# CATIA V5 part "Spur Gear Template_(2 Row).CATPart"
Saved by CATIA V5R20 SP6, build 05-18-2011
Part number: Spur Gear Template_(2 Row)
Bounding box of the stored display mesh (mm): x 0 to 42, y -40.991 to 40.991, z -40.924 to 40.992
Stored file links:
  E:\#01 CATIA Lecture Materials\#06 DMU\#10 Kinematics Joints\#002 Gear Joint(Spur Gear)\Spur Gear Template_(2 Row).CATPart
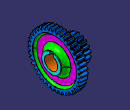
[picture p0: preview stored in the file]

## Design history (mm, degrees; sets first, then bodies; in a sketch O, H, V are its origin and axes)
Set1 "Reference Data"
  Point1 "Center Point": (0, 0, 0)
  Set2 "Datum Plane Body"
    Plane1 "Plane.1(YZ Offset Plane=42mm)": type Offset, RefPlane yz-plane, Offset 42
    Plane2 "Plane.2(Plane1 Offset Plane=-5mm)": type Offset, RefPlane Plane1, Offset -5
    Plane3 "Plane.3(Plane2 Offset Plane=-11mm)": type Offset, RefPlane Plane2, Offset -11
Body1 (main body)
  Body2 "Spur Gear Body(Z=39)"
    Pad1: profile Join2, length 11
    Sketch1 on zx-plane, origin (0, 0, 0), H (-1, 0, 0), V (0, 0, 1)
      axis line L1 (0, 0) -> (6.502, 0)
      line L2 (0, 0) -> (0, 40)
      line L3 (-1, 41) -> (-10, 41)
      line L4 (-11, 40) -> (-11, 0)
      point P2 (-11, 0)
      line L5 (-11, 0) -> (0, 0)
      line L6 (-10, 41) -> (-11, 40)
      point P3 (-11, 40)
      line L7 (-1, 41) -> (0, 40)
      point P4 (0, 40)
      construction line L8 (-11, 40) -> (0, 40)
      distance H L3 = 41 {= ra}
      distance L2 L4 = 11 {= Pad1.FirstLimit.Length}
      angle L2 L7 = 45 {= Sketch1.angle(L6 L4)}
      angle L6 L4 = 45
      distance L3 L8 = 1
      horizontal: L1 H, L3 H, L5 H, L8 H
      vertical: L2 V, L4 V
      coincidence: P2 H, P3 L4, P4 L2, P3 L6, P4 L7
    Groove1: profile Sketch1, axis Sketch1.L1, angle 360
    Set3 "Reference Data"
      Point2 "Center Point": (0, 0, 0)
      Line1 "Axis (X Direction)": type PtDir, RefPoint Point2, Direction yz-plane, Start 0, End 20
      Point3 "Involute Curve Point_01": (0, 0, 36.648)
      Point4 "Involute Curve Point_02": (0, 0.375, 38.4121)
      Point5 "Involute Curve Point_03": (0, 2.9122, 43.1836)
      Point6 "Involute Curve Point_04": (0, 9.3468, 49.4846)
      Point7 "Involute Curve Point_05": (0, 20.6231, 55.1241)
      Curve1 "Involute Curve": Elements (Point3; Point4; Point5; Point6; Point7)
      Extrapol1: ToExtrapol Point3, Support Curve1, Length 4 {= m * 2}
      Rotate1: ToTransfor Extrapol1, Axis Line1, Angle 3.1617 {= phi}
      Circle1: type CtrRad, Start 0, End 180, Center Point2, Support yz-plane, Radius 41 {= ra}, FirstDirection (0, 1, 0)
      Circle2: type CtrRad, Start 0, End 180, Center Point2, Support yz-plane, Radius 36.5 {= rf}, FirstDirection (0, 1, 0)
      Corner1: Element1 Rotate1, Element2 Circle2, Radius 0.76 {= rc}
      Set4 "Corner Operation Body"
        Sketch2 on yz-plane, origin (0, 0, 0), H (0, 1, 0), V (0, 0, 1)
          projected curve E1 from edge of Rotate1
          projected curve E2 from edge of Rotate1
          projected curve E3 from edge of Rotate1
          point P1 (-2.2538, 32.5983)
          projected arc E4 centre (0, 0) radius 36.5 from (36.5, 0) to (-36.5, 0) ccw from Circle2
          projected arc E5 centre (0, 0) radius 36.5 from (-2.0319, 36.4434) to (-2.6738, 36.4019) ccw from Circle2
          projected arc E6 centre (0, 0) radius 36.5 from (-2.6738, 36.4019) to (-36.5, 0) ccw from Circle2
          point P3 (36.5, 0)
          arc A1 centre (-2.7295, 37.1599) radius 0.76 from (-1.9747, 37.0708) to (-2.6738, 36.4019) cw
          radius A1 = 0.76 {= rc}
          coincidence: E1 P1, E4 P3
          tangency: A1 E1, A1 E4
        Extrude1: Element1 Rotate1, Lim1 5, Lim2 5, Direction yz-plane
        Extrude2: Element1 Circle2, Lim1 5, Lim2 5, Direction yz-plane
        Intersect1: ToIntersect1 Extrude1, ToIntersect2 yz-plane
        Intersect2: ToIntersect1 Extrude2, ToIntersect2 yz-plane
        Corner2: Element1 Intersect1, Element2 Intersect2, Radius 0.76 {= rc}
      Plane4 "Plane.1(ZX Plane Rotate=9deg)": type Angle, RefPlane zx-plane, Direction Line1, Angle 4.6154 {= 180deg / Z}
      Symmetry1: ToTransfor Corner1, Reference Plane4
      Split1: ToCut Rotate1, Cutting (Circle1; Corner1)
      Symmetry2: ToTransfor Split1, Reference zx-plane
      Point8: type OnCurve, Support Symmetry2, Ratio 1
      Point9: type OnCurve, Support Split1, Ratio 1
      Point10: type OnCurve, Support Corner1, Ratio 1
      Point11: type OnCurve, Support Symmetry1, Ratio 1
      Circle3: type 2PointsRad, Start 0, End 180, FirstPoint Point9, SecondPoint Point8, Support yz-plane, Radius 41 {= ra}
      Circle4: type 2PointsRad, Start 0, End 180, FirstPoint Point10, SecondPoint Point11, Support yz-plane, Radius 36.5 {= rf}
      Join1: Elements (Symmetry2; Circle3; Split1; Corner1; Circle4; Symmetry1)
      CircPattern1: of Join1, instances 39 {= Z}, angular step 9.2308 {= 360.0*1 deg/CircPattern1.AngularNumber}, axis from Line1
      Join2: Elements (Join1; CircPattern1)
    Translate1: ToTransfor Groove1, Direction yz-plane, Length 26 {= Plane1.Offset - ( - Plane2.Offset + ( - Plane3.Offset )  )}
  Assemble1: tool Body2
  Body3 "Spur Gear Body(Z=18)"
    Pad2: profile Join4, length 10
    Sketch3 on zx-plane, origin (0, 0, 0), H (-1, 0, 0), V (0, 0, 1)
      axis line L1 (0, 0) -> (6.502, 0)
      line L2 (0, 0) -> (0, 19)
      line L3 (-1, 20) -> (-9, 20)
      line L4 (-10, 19) -> (-10, 0)
      point P2 (-10, 0)
      line L5 (-10, 0) -> (0, 0)
      line L6 (-9, 20) -> (-10, 19)
      point P3 (-10, 19)
      line L7 (-1, 20) -> (0, 19)
      point P4 (0, 19)
      construction line L8 (-10, 19) -> (0, 19)
      distance H L3 = 20 {= ra}
      distance L2 L4 = 10 {= Pad2.FirstLimit.Length}
      angle L2 L7 = 45 {= Sketch3.angle(L6 L4)}
      angle L6 L4 = 45
      distance L3 L8 = 1
      horizontal: L1 H, L3 H, L5 H, L8 H
      vertical: L2 V, L4 V
      coincidence: P2 H, P3 L4, P4 L2, P3 L6, P4 L7
    Groove2: profile Sketch3, axis Sketch3.L1, angle 360
    Set5 "Reference Data"
      Point12 "Center Point": (0, 0, 0)
      Line2 "Axis (X Direction)": type PtDir, RefPoint Point12, Direction yz-plane, Start 0, End 20
      Point13 "Involute Curve Point_01": (0, 0, 16.9145)
      Point14 "Involute Curve Point_02": (0, 0.1731, 17.7287)
      Point15 "Involute Curve Point_03": (0, 1.3441, 19.9309)
      Point16 "Involute Curve Point_04": (0, 4.3139, 22.839)
      Point17 "Involute Curve Point_05": (0, 9.5184, 25.4419)
      Curve2 "Involute Curve": Elements (Point13; Point14; Point15; Point16; Point17)
      Extrapol2: ToExtrapol Point13, Support Curve2, Length 4 {= m * 2}
      Rotate2: ToTransfor Extrapol2, Axis Line2, Angle 5.854 {= phi}
      Circle5: type CtrRad, Start 0, End 180, Center Point12, Support yz-plane, Radius 20 {= ra}, FirstDirection (0, 1, 0)
      Circle6: type CtrRad, Start 0, End 180, Center Point12, Support yz-plane, Radius 15.5 {= rf}, FirstDirection (0, 1, 0)
      Corner3: Element1 Rotate2, Element2 Circle6, Radius 0.76 {= rc}
      Set6 "Corner Operation Body"
        Sketch4 on yz-plane, origin (0, 0, 0), H (0, 1, 0), V (0, 0, 1)
          projected curve E1 from edge of Rotate2
          projected curve E2 from edge of Rotate2
          projected curve E3 from edge of Rotate2
          point P1 (-1.7679, 12.8258)
          projected arc E4 centre (0, 0) radius 15.5 from (15.5, 0) to (-15.5, 0) ccw from Circle6
          projected arc E5 centre (0, 0) radius 15.5 from (-1.7414, 15.4019) to (-2.378, 15.3165) ccw from Circle6
          projected arc E6 centre (0, 0) radius 15.5 from (-2.378, 15.3165) to (-15.5, 0) ccw from Circle6
          point P3 (15.5, 0)
          arc A1 centre (-2.4946, 16.0675) radius 0.76 from (-1.7347, 16.0597) to (-2.378, 15.3165) cw
          radius A1 = 0.76 {= rc}
          coincidence: E1 P1, E4 P3
          tangency: A1 E1, A1 E4
        Extrude3: Element1 Rotate2, Lim1 5, Lim2 5, Direction yz-plane
        Extrude4: Element1 Circle6, Lim1 5, Lim2 5, Direction yz-plane
        Intersect3: ToIntersect1 Extrude3, ToIntersect2 yz-plane
        Intersect4: ToIntersect1 Extrude4, ToIntersect2 yz-plane
        Corner4: Element1 Intersect3, Element2 Intersect4, Radius 0.76 {= rc}
      Plane5 "Plane.1(ZX Plane Rotate=9deg)": type Angle, RefPlane zx-plane, Direction Line2, Angle 10 {= 180deg / Z}
      Symmetry3: ToTransfor Corner3, Reference Plane5
      Split2: ToCut Rotate2, Cutting (Circle5; Corner3)
      Symmetry4: ToTransfor Split2, Reference zx-plane
      Point18: type OnCurve, Support Symmetry4, Ratio 1
      Point19: type OnCurve, Support Split2, Ratio 1
      Point20: type OnCurve, Support Corner3, Ratio 1
      Point21: type OnCurve, Support Symmetry3, Ratio 1
      Circle7: type 2PointsRad, Start 0, End 180, FirstPoint Point19, SecondPoint Point18, Support yz-plane, Radius 20 {= ra}
      Circle8: type 2PointsRad, Start 0, End 180, FirstPoint Point20, SecondPoint Point21, Support yz-plane, Radius 15.5 {= rf}
      Join3: Elements (Symmetry4; Circle7; Split2; Corner3; Circle8; Symmetry3)
      CircPattern2: of Join3, instances 18 {= Z}, angular step 20 {= 360.0*1 deg/CircPattern2.AngularNumber}, axis from Line2
      Join4: Elements (Join3; CircPattern2)
  Assemble2: tool Body3
  Body4 "Hole Boss Body"
    Sketch5 on yz-plane, origin (0, 0, 0), H (0, 1, 0), V (0, 0, 1)
      circle A1 centre (0, 0) radius 14.5
      radius A1 = 14.5
    Pad3: profile Sketch5, direction (1, 0, 0), up to Plane1
  Assemble3: tool Body4
  Body5 "Key Hole Body"
    Sketch6 on yz-plane, origin (0, 0, 0), H (0, 1, 0), V (0, 0, 1)
      arc A1 centre (0, 0) radius 10 from (-3, 9.5394) to (3, 9.5394) ccw
      line L1 (-3, 12.8) -> (3, 12.8)
      line L2 (3, 12.8) -> (3, 9.5394)
      line L3 (-3, 9.5394) -> (-3, 12.8)
      radius A1 = 10
      distance L3 L2 = 6
      distance L1 A1 = 22.8
      horizontal: L1 H
      vertical: L2 V, L3 V
      symmetry: L3 L2 V
    Pad4: profile Sketch6, direction (1, 0, 0), up to Plane1
  Remove1: tool Body5
  Body6 "Remove Pocket Body"
    Body7 "Pocket Body"
      Sketch7 on Plane2, origin (37, 0, 0), H (0, 1, 0), V (0, 0, 1)
        circle A1 centre (0, 0) radius 33.5
        projected circle E1 centre (0, 0) radius 14.5 from edge [face of Pad3 from Sketch5.A1 | end face of Pad3]
        radius A1 = 33.5
      Pad5: profile Sketch7, direction (-1, 0, 0), length 3.5
    Assemble4: tool Body7
    Body8 "Pocket Body"
      Sketch8 on Plane3, origin (26, 0, 0), H (0, 1, 0), V (0, 0, 1)
        circle A1 centre (0, 0) radius 33.5
        projected circle E1 centre (0, 0) radius 14.5 from edge [face of Pad3 from Sketch5.A1 | end face of Pad3]
        radius A1 = 33.5
      Pad6: profile Sketch8, direction (1, 0, 0), length 3.5
    Assemble5: tool Body8
  Remove2: tool Body6
  Fillet1: radius 7, on edge [end face of Pad5 | face of Pad3]; edge [face of Pad3 | end face of Pad6]
  Fillet2: radius 3, on edge [face of Pad5 from Sketch7.A1 | end face of Pad5]; edge [end face of Pad6 | face of Pad6 from Sketch8.A1]
  Fillet3: radius 1, on edge [face of Groove2 from Sketch3.L4 | face of Pad3]
Relations
  rp = m * Z / 2
  ra = rp + m
  rb = rp * cos( a  )
  rf = rp -1.25 * m
  rc = m * 0.38
  c = sqrt( 1 / ( cos( a ) * cos( a ) ) - 1 ) / PI
  rp = m * Z / 2
  ra = rp + m
  rb = rp * cos( a  )
  rf = rp -1.25 * m
  rc = m * 0.38
  c = sqrt( 1 / ( cos( a ) * cos( a ) ) - 1 ) / PI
